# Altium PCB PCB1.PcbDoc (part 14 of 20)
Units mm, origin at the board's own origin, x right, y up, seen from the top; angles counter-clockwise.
Board outline 294.51 x 138.18 mm, 12 copper layers (Top Layer 1 _Signal, L2_GND, L3_Signals, L4_GND, L5_POWER, L6_Signals, L7_GND, L8_Signals, L9_GND, L10_POWER, L11_GND, Bottom Layer_Signals), stack 1.788 mm thick; 1254 components, 836 nets, 5699 pads, 2073 vias.
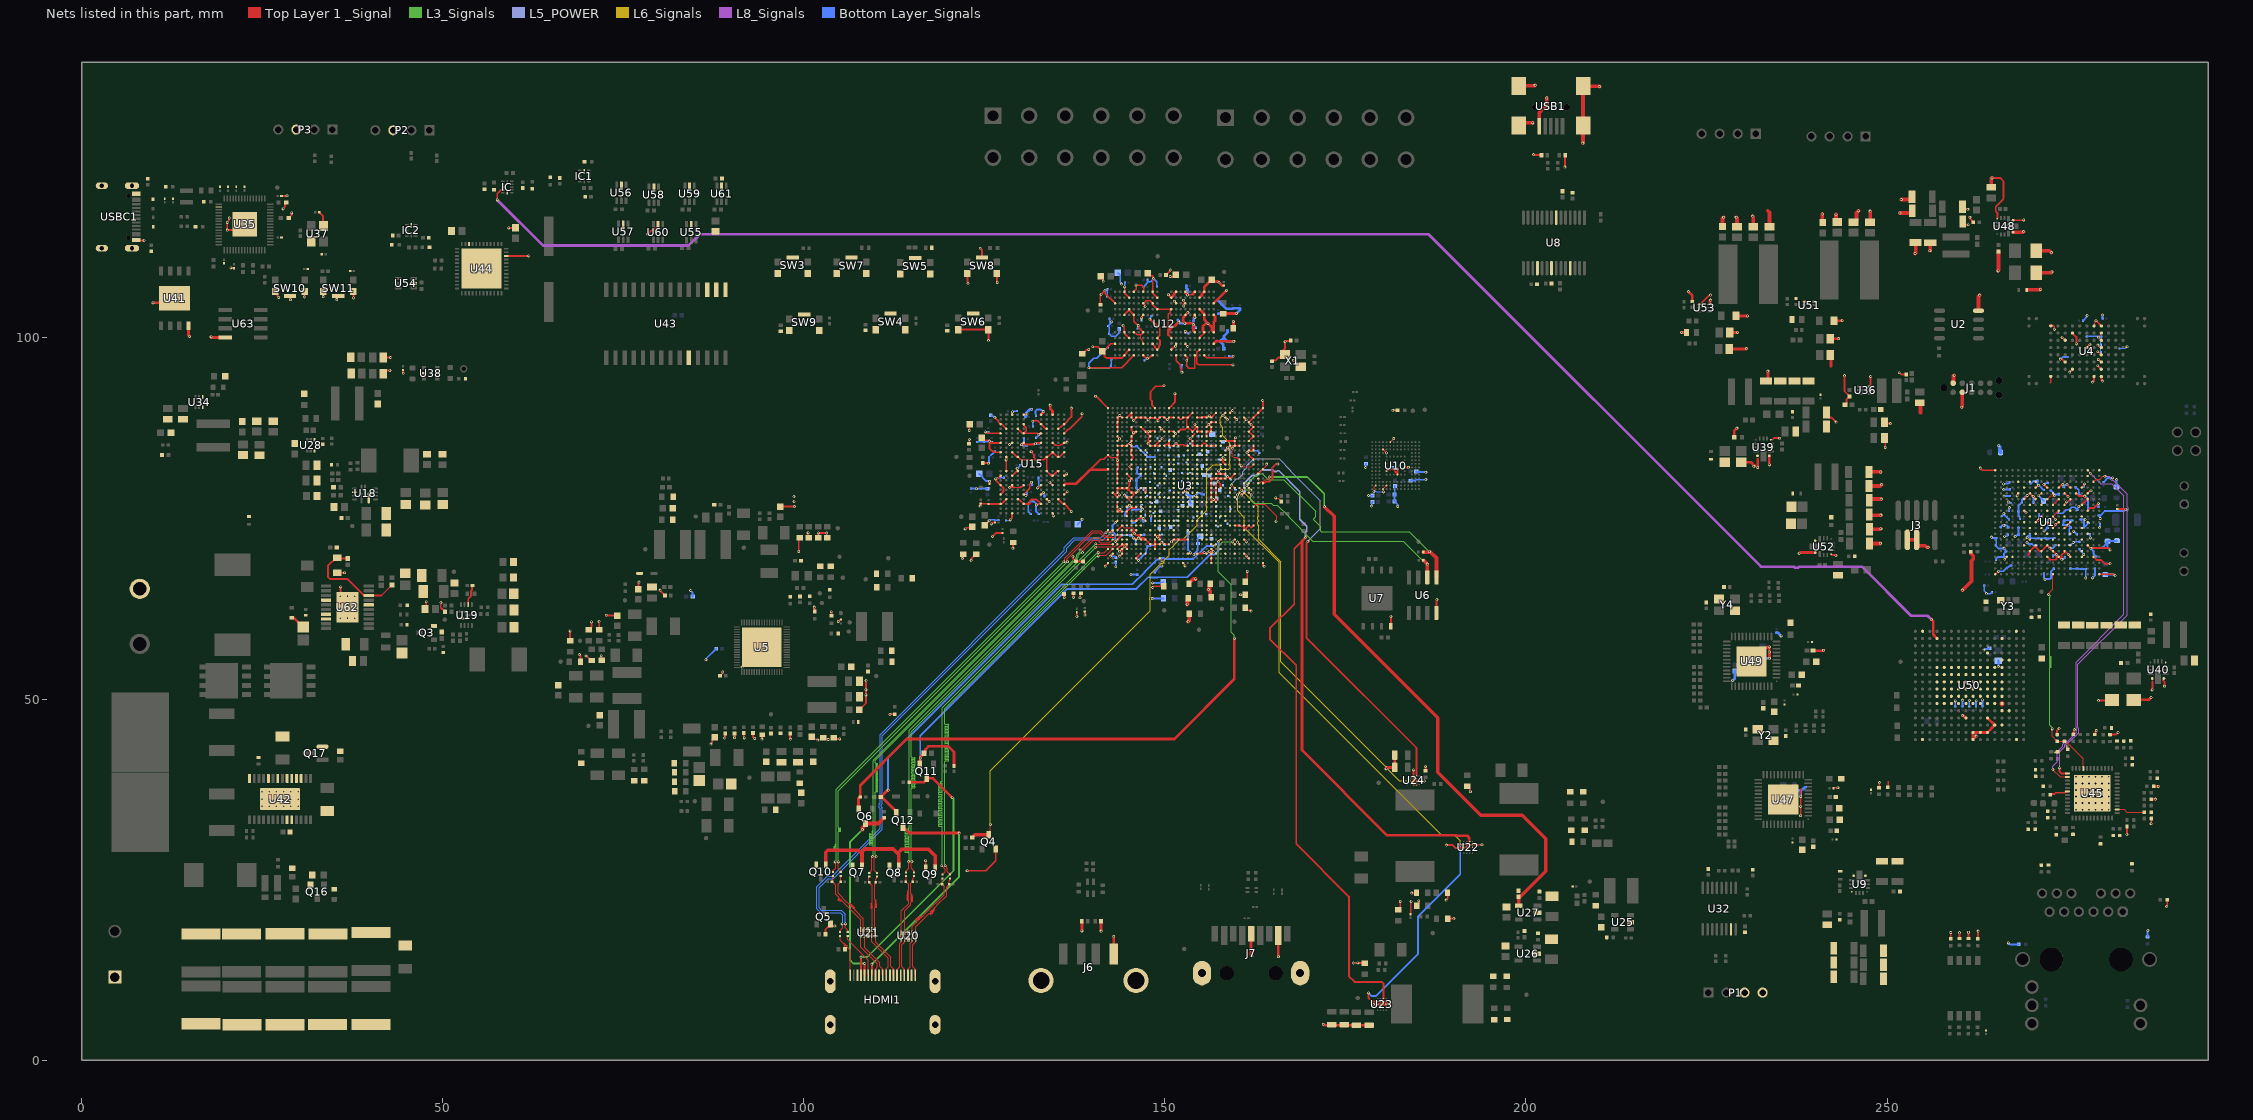
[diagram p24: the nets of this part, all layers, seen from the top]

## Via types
v1: diameter 0.4, hole 0.2, Top Layer 1 _Signal to Bottom Layer_Signals, 2009 vias
v2: diameter 0.508, hole 0.254, Top Layer 1 _Signal to Bottom Layer_Signals, 36 vias
v3: diameter 0.5, hole 0.2, Top Layer 1 _Signal to Bottom Layer_Signals, 12 vias
v4: diameter 1.27, hole 0.711, Top Layer 1 _Signal to Bottom Layer_Signals, 6 vias
v5: diameter 0.3, hole 0.2, Top Layer 1 _Signal to Bottom Layer_Signals, 5 vias
v6: diameter 0.254, hole 0.2, Top Layer 1 _Signal to Bottom Layer_Signals, 3 vias
v7: diameter 0.305, hole 0.2, Top Layer 1 _Signal to Bottom Layer_Signals, 1 vias
v8: diameter 0.254, hole 0.152, Top Layer 1 _Signal to Bottom Layer_Signals, 1 vias

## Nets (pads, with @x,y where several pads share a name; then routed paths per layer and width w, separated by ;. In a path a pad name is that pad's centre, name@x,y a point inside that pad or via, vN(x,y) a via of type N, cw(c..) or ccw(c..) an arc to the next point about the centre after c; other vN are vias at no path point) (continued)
GND: (continued)
  Bottom Layer_Signals w0.254: v1(84.325,65.024) 84.613,64.736 R40.2@84.613,64.197 ; v1(86.437,55.437) 86.465,55.465 86.465,55.562 C175.2@87.879,56.976 ; C424.2@123.168,79.148 123.181,79.135 123.893,79.135 v1(123.913,79.116) ; v1@123.893,79.148 123.929,79.113 124.764,79.113 124.782,79.132 125.41,79.132 C551.2@125.423,79.118 ; C413.2@124.27,81.195 125.286,80.179 125.702,80.179 v1(125.73,80.151) ; v1(125.557,82.641) 125.557,82.648 125.639,82.73 C403.2@125.639,83.442 125.652,83.455 125.652,83.513 126.033,83.895 126.106,83.895 126.479,84.267 C404.2@126.489,84.267 ; v1(125.657,74.692) 125.697,74.692 125.832,74.828 126.45,74.828 126.52,74.757 126.964,74.757 C419.2@126.966,74.76 ; v1(126.574,80.474) 126.613,80.474 126.774,80.634 C408.2@127.736,80.634 ; v1(128.899,89.753) 128.939,89.753 129.022,89.836 129.533,89.836 C427.2@129.546,89.849 ; v1(129.535,81.93) 129.563,81.958 129.606,81.958 129.941,82.293 129.941,82.351 C411.2@129.954,82.364 ; C405.2@130.521,86.05 130.508,86.037 130.508,85.597 130.157,85.246 v1(130.157,85.207) 130.197,85.207 130.282,85.122 C406.2@130.876,85.122 ; v1(130.752,78.181) 130.752,78.22 130.928,78.396 130.928,78.63 C418.2@130.941,78.643 ; C426.2@131.435,75.628 131.425,75.628 131.246,75.808 131.198,75.808 131.074,75.931 131.074,77.125 131.291,77.342 131.918,77.342 132.159,77.101 132.159,77.041 132.2,77 132.2,76.897 v1(132.228,76.869) 132.228,76.829 132.178,76.779 132.178,75.943 132.301,75.82 132.349,75.82 132.529,75.641 C423.2@132.539,75.641 ; v1(131.522,80.023) 131.522,79.984 131.6,79.907 131.6,79.637 C400.2@131.613,79.624 ; C422.2@132.138,89.223 132.128,89.223 132.115,89.236 132.115,89.446 132.11,89.451 132.11,89.926 132.259,90.075 132.788,90.075 132.831,90.031 132.889,90.031 133.116,89.803 v1(133.156,89.803) ; v1(132.381,79.242) 132.381,79.282 132.534,79.435 132.534,80.285 132.492,80.327 132.492,80.672 C396.2@132.479,80.685 ; v1(133.17,78.615) 133.17,78.575 133.298,78.448 133.298,78.087 C416.2@133.311,78.074 ; C394.2@137.945,74.178 138.486,74.72 138.486,74.852 v1(138.532,74.898) ; v1(143.14,71.82) 143.14,72.827 142.728,73.239 142.728,73.982 143.152,74.407 v1(143.152,74.424) ; R104.2@143.951,72.673 145.28,72.673 145.641,72.312 v1(145.681,72.312) 145.681,72.284 145.964,72.001 C17.1@145.964,71.489 ; v1(144.398,78.237) 144.426,78.209 144.654,78.209 144.923,77.94 C284.1@144.933,77.94 ; v1(145.184,85.379) 145.212,85.351 145.212,85.296 145.569,84.939 145.909,84.939 145.985,85.014 146.158,85.014 C298.1@146.171,85.027 ; v1(145.313,67.26) 145.325,67.248 146.165,67.248 R176.2@146.177,67.236 ; C203.2@145.508,74.398 145.508,74.444 145.512,74.448 145.869,74.448 146.401,74.98 v1@146.965,74.98 ; C32.2@145.525,76.232 146.792,76.232 146.853,76.294 v1(146.893,76.294) ; C292.2@146.067,80.265 C292.2@146.076,80.265 ; C298.1@146.171,85.029 C298.1@146.171,85.027 ; C287.2@146.217,82.05 146.171,82.05 146.167,82.046 146.167,81.615 146.124,81.573 146.124,81.362 146.343,81.143 146.502,81.143 146.668,80.978 C291.1@146.668,80.968 146.668,80.958 146.117,80.407 146.117,80.269 146.113,80.265 C292.2@146.076,80.265 ; v1(146.3,78.808) 146.272,78.836 146.272,78.993 146.078,79.186 C290.1@146.078,79.196 146.073,79.202 146.073,80.262 C292.2@146.076,80.265 ; v1(146.339,72.281) 146.367,72.309 146.367,72.399 146.684,72.716 147.09,72.716 147.103,72.729 C471.1@147.103,72.739 ; v1@146.956,74.989 v1@146.965,74.98 ; v1(147.004,74.98) v1@146.965,74.98 ; C310.1@147.065,74.552 147.055,74.552 147.042,74.565 147.042,74.903 v1@146.965,74.98 ; v1(148.072,75.34) 148.08,75.333 148.08,74.675 C462.1@148.087,74.668 ; v1(148.254,63.913) 149.799,63.913 C237.2@149.813,63.926 ; v1(148.297,66.082) 149.655,66.082 C238.2@149.776,66.203 ; C308.1@148.58,83.528 147.614,83.528 146.184,84.958 146.184,85.014 C298.1@146.171,85.027 ; R91.1@148.595,67.58 148.595,67.605 148.643,67.653 148.668,67.653 148.859,67.844 148.859,67.867 149.329,68.336 149.478,68.336 149.558,68.416 v1(149.597,68.416) ; C263.1@153.081,78.376 153.081,78.351 153.204,78.228 153.411,78.228 ; C264.2@153.217,73.008 153.217,70.634 153.57,70.281 v1(153.57,70.242) ; C263.1@153.295,78.344 153.411,78.228 ; C247.2@153.586,77.092 153.494,77.184 153.494,78.145 153.411,78.228 ; C229.2@155.43,78.324 155.417,78.337 155.036,78.337 154.868,78.505 154.658,78.505 154.286,78.134 153.53,78.134 153.436,78.228 153.411,78.228 ; v1(158.698,84.801) 158.726,84.773 158.726,84.563 159.086,84.202 C455.1@159.086,84.157 ; v1(177.795,82.059) 177.815,82.08 177.815,82.567 C216.1@177.836,82.588 ; v1(178.198,78.183) 178.227,78.155 C211.1@178.759,78.155 ; v1(178.622,76.704) 178.65,76.732 178.65,77.189 C214.1@178.745,77.284 ; C207.1@181.506,81.981 181.594,81.893 182.185,81.893 v1(182.213,81.865) ; C217.1@181.87,79.475 181.831,79.435 181.831,78.336 C213.1@181.791,78.296 181.787,78.292 181.787,77.361 C210.1@181.782,77.357 181.802,77.357 182.214,76.945 182.214,76.71 v1(182.242,76.682) ; C209.2@184.019,80.211 184.044,80.236 184.65,80.236 184.777,80.363 186.143,80.363 v1(186.154,80.375) ; C208.1@184.808,81.494 184.876,81.426 186.108,81.426 v1(186.136,81.398) ; C614.1@259.443,48.986 259.443,49.673 259.444,49.674 v1(259.444,49.75) ; C615.2@260.464,48.979 v1(260.464,49.851) v1@260.469,49.856 ; C613.1@261.385,48.99 261.385,49.8 v1(261.399,49.814) ; C617.2@262.336,48.994 262.34,48.998 262.34,49.747 v1(262.355,49.761) ; v1(263.22,49.871) 263.22,49.851 263.232,49.839 C616.2@263.232,49.016 ; v1(263.412,56.779) 263.558,56.925 264.055,56.925 C611.1@264.178,57.048 ; v1(264.457,72.426) 264.463,72.426 264.589,72.299 C119.2@265.132,72.299 265.132,71.314 265.075,71.256 265.088,71.243 265.088,71.223 265.203,71.108 265.203,71.059 265.418,70.845 266.107,70.845 266.164,70.902 v1(266.204,70.902) 266.204,70.863 266.388,70.679 266.388,70.356 C81.2@266.401,70.343 266.401,70.333 266.196,70.128 266.196,69.676 ; C113.2@265.073,69.275 265.086,69.288 265.086,69.298 265.202,69.413 265.202,69.462 265.416,69.676 266.196,69.676 ; C619.1@265.403,55.319 265.416,55.306 v1(265.416,54.488) ; v1(265.452,67.682) 266.075,67.682 266.635,68.242 266.763,68.242 266.991,68.47 267.189,68.47 267.202,68.483 C114.2@267.202,68.493 ; C78.2@265.752,73.827 265.762,73.827 265.971,74.036 266.152,74.036 v1(266.18,74.064) 266.207,74.036 266.588,74.036 266.844,73.78 C83.2@266.844,73.77 C83.2@266.857,73.757 ; C85.2@265.897,75.316 265.907,75.316 266.156,75.565 266.156,75.656 v1(266.184,75.684) 266.184,75.585 266.916,74.853 C79.2@266.916,74.843 ; v1(266.13,79.798) 266.751,79.798 266.956,80.004 266.966,80.004 266.979,80.017 C108.2@266.979,80.027 ; v1(266.15,79.006) 266.156,79.013 266.987,79.013 267.001,79.027 267.011,79.027 267.024,79.04 C82.2@267.024,79.05 ; v1(266.2,78.098) 267.034,78.098 267.047,78.111 C80.2@267.047,78.114 ; v1(266.265,72.517) 266.293,72.545 266.573,72.545 266.764,72.736 C84.2@266.764,72.746 ; v1(266.308,69.361) 266.304,69.365 266.304,69.676 266.196,69.676 ; v1(266.783,16.228) 266.823,16.228 267.023,16.028 R399.2@268.241,16.028 ; v1(266.785,77.28) 266.813,77.252 267.004,77.252 267.085,77.171 267.095,77.171 267.108,77.158 C86.2@267.108,77.148 ; C87.2@266.868,76.02 266.881,76.033 266.881,76.402 266.948,76.469 v1(266.948,76.509) ; v1(267.724,72.491) 267.727,72.491 267.903,72.667 268.194,72.667 268.207,72.68 C145.2@268.207,72.69 268.212,72.695 268.212,73.743 268.218,73.748 C148.2@268.218,73.766 ; C144.2@268.39,74.922 268.377,74.935 268.377,75.246 268.209,75.413 C150.2@268.209,75.944 268.209,76.769 268.663,77.223 C142.2@268.663,77.233 268.676,77.246 268.676,77.573 269.283,78.18 v1(269.414,78.18) ; v1(269.379,71.652) 269.419,71.652 269.591,71.48 269.981,71.48 270.006,71.454 270.055,71.454 270.222,71.287 270.69,71.287 270.703,71.274 C191.2@270.703,71.264 ; v1(269.406,72.325) 269.434,72.353 269.434,72.454 269.803,72.823 C143.2@269.813,72.823 269.813,72.409 269.962,72.26 270.956,72.26 270.958,72.258 C152.2@270.979,72.258 271.893,72.258 271.957,72.195 C151.2@271.967,72.195 271.98,72.208 272.491,72.208 272.547,72.263 C138.2@273.186,72.263 ; C107.2@269.896,79.82 269.896,79.83 270.298,80.232 C95.2@270.848,80.232 270.848,79.772 270.987,79.634 v1(270.987,79.594) 271.015,79.566 271.061,79.566 271.713,78.914 C134.2@271.723,78.914 ; v1(270.227,78.083) 270.293,78.017 C147.2@270.293,77.167 ; v1(271.015,78.148) 271.015,78.145 271.683,77.477 C121.1@271.683,77.423 ; v1(271.71,79.696) 271.75,79.696 271.931,79.878 272.265,79.878 272.278,79.891 C93.2@272.278,79.901 ; C102.2@271.74,67.378 271.74,66.747 271.874,66.612 v1(271.874,66.573) 271.902,66.601 272.568,66.601 272.717,66.749 272.717,67.667 273.076,68.026 273.086,68.026 C96.2@273.099,68.039 ; v1(272.554,70.902) 272.947,70.902 273.343,71.299 C123.2@273.343,71.309 ; C135.2@272.664,78.863 272.674,78.863 272.752,78.785 272.8,78.785 273.201,78.384 v1(273.201,78.177) 273.241,78.177 273.391,78.327 273.805,78.327 273.818,78.34 C116.2@273.818,78.35 ; C129.2@272.988,69.885 273.001,69.898 273.346,69.898 273.449,70.002 v1(273.488,70.002) ; v1(273.993,97.069) 274.032,97.069 274.322,97.358 C11.1@274.987,97.358 ; v1(274.201,69.351) 274.229,69.379 274.41,69.379 274.64,69.61 C154.2@274.65,69.61 ; C130.2@274.411,74.089 v1@275.063,74.088 ; C104.2@274.432,79.369 274.432,79.379 274.663,79.61 274.663,79.66 274.894,79.66 v1(274.922,79.688) ; v1@275.102,73.996 275.229,73.996 275.449,73.777 C140.2@275.449,73.767 275.449,73.757 275.239,73.547 275.239,72.791 C127.2@275.243,72.787 ; C122.2@275.211,71.344 275.211,71.354 275.224,71.367 275.467,71.367 275.772,71.672 v1(275.812,71.672) 275.851,71.672 275.951,71.772 C139.2@276.665,71.772 ; C100.2@275.379,68.045 275.382,68.048 276.374,68.048 C131.2@276.377,68.05 276.39,68.037 276.694,68.037 276.724,68.007 277.052,68.007 ; v1(275.808,73.215) 275.836,73.188 275.914,73.188 276.273,72.828 C153.2@276.273,72.818 ; C99.2@276.107,79.335 276.107,79.325 276.38,79.051 276.478,79.051 276.557,78.972 276.557,78.484 276.583,78.458 276.583,78.448 276.788,78.243 276.788,78.103 277.374,78.103 v1(277.377,78.1) 277.405,78.072 277.535,78.072 277.825,77.783 277.825,76.942 277.808,76.926 C155.2@277.808,76.158 ; C190.2@276.635,70.759 276.635,70.749 276.763,70.62 276.763,70.541 277.209,70.096 277.209,70.073 277.238,70.043 v1(277.238,70.023) ; C156.2@276.773,74.876 277.352,74.876 277.395,74.832 v1(277.435,74.832) 277.435,74.793 277.274,74.632 C136.2@277.274,73.784 ; 277.056,68.007 277.192,68.007 277.195,68.004 277.511,68.004 v1(277.511,66.757) ; C14.1@277.143,102.382 277.143,102.392 277.677,102.926 277.677,103.07 v1(277.705,103.098) ; C136.2@277.274,73.774 C136.2@277.274,73.784 ; C105.2@277.282,79.4 277.289,79.4 277.302,79.413 277.302,79.763 v1(277.323,79.784) ; C103.2@277.512,68.004 C103.2@277.525,67.991 ; C13.1@277.66,100.226 v1@279.32,100.226 ; C98.2@277.935,74.393 277.925,74.393 277.329,73.797 277.287,73.797 C136.2@277.274,73.784 ; C149.2@278.123,72.818 278.136,72.805 278.136,72.368 278.152,72.351 278.152,72.328 v1(278.16,72.321) ; v1(278.225,70.875) 278.225,70.835 278.594,70.467 278.594,70.085 278.843,69.836 278.879,69.836 278.958,69.757 C92.2@278.968,69.757 ; v1(278.461,66.773) 278.813,67.125 278.813,67.902 278.809,67.906 278.809,68.027 278.796,68.04 C101.2@278.786,68.04 ; v1(279.269,77.098) 279.284,77.082 279.284,76.61 C94.2@279.297,76.597 ; v1@279.359,100.13 279.375,100.13 279.442,100.196 279.693,100.196 C9.1@279.706,100.209 ; v1(279.438,73.74) 279.438,73.779 279.482,73.823 279.482,74.194 C89.2@279.495,74.207 ; v1(279.527,74.996) 279.499,75.024 279.499,75.224 279.299,75.425 C90.2@279.299,75.435 279.299,75.445 279.312,75.458 279.588,75.458 280.179,76.048 C111.2@280.189,76.048 282.852,76.048 v1(283.07,76.266) ; v1(279.829,103.179) 279.829,103.139 279.859,103.11 279.859,102.706 C6.1@279.872,102.693 ; C91.2@279.843,70.956 279.853,70.956 280.299,71.402 C133.1@280.299,71.627 ; C112.2@279.972,80.024 279.982,80.024 280.569,80.611 v1(281.229,80.611) ; C106.1@280.212,67.222 281.406,67.222 281.547,67.081 v1(281.586,67.081) ; v1(280.881,70.656) 280.881,70.696 280.542,71.035 280.542,71.627 C133.1@280.299,71.627 ; C97.1@281.773,79.356 281.773,80.371 v1(281.787,80.385) 281.796,80.385 v1@281.801,80.38 ; C132.1@281.836,71.921 281.799,71.884 280.579,71.884 C133.1@280.542,71.846 280.518,71.846 C133.1@280.299,71.627 ; C380.2@286.073,17.075 286.073,17.876 286.124,17.928 v1(286.124,17.967)
  Bottom Layer_Signals w0.381: C428.2@130.683,89.055 130.799,89.171 130.799,89.578 131.351,90.13 v1(131.566,90.13) ; C319.2@151.792,102.479 151.896,102.376 151.896,102.228 152.096,102.028 152.776,102.028 v1(152.78,102.024) ; C320.2@152.963,107.235 152.963,106.903 153.128,106.738 153.128,105.971 v1(153.132,105.967) ; C332.2@153.997,102.35 153.997,102.677 154.15,102.83 v1(154.15,102.835) ; C333.2@157.407,103.355 158.635,103.355 158.679,103.398 v1(159.912,103.398) 160.389,103.875 C358.2@160.389,104.054 160.321,104.122 159.431,104.122 C345.2@159.341,104.032 158.515,104.032 C357.2@157.445,105.102 ; C388.2@158.141,98.504 158.072,98.573 158.072,99.084 157.771,99.385 C342.2@157.771,99.7 157.846,99.625 158.18,99.959 ; C331.2@158.667,101.052 158.667,100.762 158.18,100.275 158.18,99.959 ; v1(159.549,99.54) 158.599,99.54 158.18,99.959 ; v1(228.628,52.58) 228.679,52.58 228.9,52.801 C661.1@228.9,53.887 ; C658.2@232.81,55.863 233.03,55.643 233.715,55.643 v1(233.718,55.64) ; C662.2@234.675,59.176 234.888,59.176 235.334,58.73 v1(235.339,58.73) ; C24.2@235.619,36.638 235.879,36.897 236.011,36.897 236.015,36.901 236.772,36.901 237.192,37.322 C27.1@237.192,37.366 238.04,37.366 238.049,37.357 v1(238.049,36.515) ; 238.089,37.321 238.305,37.537 238.402,37.537 238.614,37.749 238.654,37.749 C28.2@238.697,37.792
  Bottom Layer_Signals w0.508: v1(265.47,85.063) 265.621,84.912 265.621,84.25 C88.1@265.717,84.154
  other v1: 238.036,35.125 24.979,35.146 25.979,35.146 26.979,35.146 27.98,35.146 28.98,35.146 29.98,35.146 24.979,36.146 25.979,36.146 26.979,36.146 27.98,36.146 28.98,36.146 29.98,36.146 24.979,37.146 25.979,37.146 26.979,37.146 27.98,37.146 28.98,37.146 29.98,37.146 263.775,64.584 98.652,77.366 98.622,78.026
  other v2: 276.149,34.678 277.059,34.678 277.969,34.678 278.879,34.678 279.789,34.678 280.699,34.678 276.149,35.588 277.059,35.588 277.969,35.588 278.879,35.588 279.789,35.588 280.699,35.588 276.149,36.498 277.059,36.498 277.969,36.498 278.879,36.498 279.789,36.498 280.699,36.498 276.149,37.408 277.059,37.408 277.969,37.408 278.879,37.408 279.789,37.408 280.699,37.408 276.149,38.318 277.059,38.318 277.969,38.318 278.879,38.318 279.789,38.318 280.699,38.318 276.149,39.228 277.059,39.228 277.969,39.228 278.879,39.228 279.789,39.228 280.699,39.228
  other v3: 35.818,61.211 36.818,61.211 37.818,61.211 35.818,62.211 36.818,62.211 37.818,62.211 35.818,63.211 36.818,63.211 37.818,63.211 36.818,64.211 37.818,64.211
HB_LM: C219.2 D9.1 U62.18 | length 2.1
  Top Layer 1 _Signal w0.381: D9.1@29.084,61.237 29.103,61.217 29.415,61.217 30.672,59.961 C219.2@30.697,59.961
HDMI0_eARC+: C465.1 HDMI1.14 | length 6.6
  Top Layer 1 _Signal w0.161: C465.1@106.082,17.213 106.082,16.659 108.925,13.816 HDMI1.14@108.925,11.745
HDMI0_eARC-: C469.1 HDMI1.19 R103.2 | length 6.7
  Top Layer 1 _Signal w0.161: C469.1@105.035,17.218 105.035,16.62 105.208,16.447 105.265,16.39 105.52,16.134 105.577,16.191 105.709,16.059 105.576,15.925 105.708,15.793 105.866,15.951 105.998,15.819 105.916,15.738 106.049,15.606 106.106,15.549 106.425,15.23 HDMI1.19@106.425,11.745
HDMI0_TX0_PORT/eDP0_TX_D0_N: C479.1 U3.AJ1 | length 66.8
  Top Layer 1 _Signal w0.111: C479.1@109.074,25.932 109.43,26.288 109.43,28.066 109.541,28.176 v1(109.541,28.179) ; v1(138.251,70.622) 138.33,70.622 138.436,70.728 138.442,70.728 139.945,72.232 140.052,72.339 140.844,72.339 141.105,72.078 U3.AJ1@142.129,72.078
  L3_Signals w0.092: v1(109.541,28.179) 109.541,28.263 109.635,28.357 109.635,29.258 109.636,29.259 109.636,29.704 109.636,29.75 ccw(c109.544,29.75) 109.544,29.842 109.134,29.842 cw(c109.134,29.927) 109.134,30.011 109.552,30.011 ccw(c109.552,30.095) 109.552,30.18 109.134,30.18 cw(c109.134,30.264) 109.134,30.348 109.552,30.348 ccw(c109.552,30.433) 109.552,30.517 109.134,30.517 cw(c109.134,30.601) 109.134,30.686 109.552,30.686 ccw(c109.552,30.77) 109.552,30.854 109.134,30.854 cw(c109.134,30.939) 109.134,31.023 109.552,31.023 ccw(c109.552,31.107) 109.552,31.192 109.134,31.192 cw(c109.134,31.276) 109.134,31.36 109.552,31.36 ccw(c109.552,31.445) 109.552,31.529 109.529,31.529 cw(c109.529,31.613) 109.529,31.698 109.544,31.698 ccw(c109.544,31.79) 109.636,31.79 109.636,32.143 109.636,38.059 109.636,39.383 109.636,41.472 109.641,41.472 109.696,41.526 109.696,41.57 137.816,69.69 137.816,69.982 138.207,70.373 138.207,70.578 v1(138.251,70.622)
HDMI0_TX0_PORT/eDP0_TX_D0_P: C478.1 U3.AJ2 | length 67.2
  Top Layer 1 _Signal w0.111: v1(110.024,28.179) 109.77,27.925 109.77,26.29 C478.1@110.126,25.934 ; v1(138.593,70.28) 138.649,70.335 138.649,70.563 140.085,71.999 140.703,71.999 141.085,71.618 142.319,71.618 U3.AJ2@142.779,72.078
  L3_Signals w0.092: v1(110.024,28.179) 110.024,28.263 109.93,28.357 109.93,29.135 109.932,29.137 109.932,36.875 109.932,37.09 cw(c110.024,37.09) 110.024,37.182 110.133,37.182 ccw(c110.133,37.267) 110.133,37.351 110.016,37.351 cw(c110.016,37.435) 110.016,37.52 110.133,37.52 ccw(c110.133,37.604) 110.133,37.688 110.016,37.688 cw(c110.016,37.773) 110.016,37.857 110.133,37.857 ccw(c110.133,37.941) 110.133,38.026 110.016,38.026 cw(c110.016,38.11) 110.016,38.194 110.133,38.194 ccw(c110.133,38.279) 110.133,38.363 110.016,38.363 cw(c110.016,38.447) 110.016,38.532 110.133,38.532 ccw(c110.133,38.616) 110.133,38.7 110.016,38.7 cw(c110.016,38.785) 110.016,38.869 110.133,38.869 ccw(c110.133,38.953) 110.133,39.038 110.016,39.038 cw(c110.016,39.122) 110.016,39.206 110.133,39.206 ccw(c110.133,39.291) 110.133,39.375 110.016,39.375 cw(c110.016,39.459) 110.016,39.544 110.133,39.544 ccw(c110.133,39.628) 110.133,39.712 110.016,39.712 cw(c110.016,39.797) 110.016,39.881 110.133,39.881 ccw(c110.133,39.965) 110.133,40.05 110.016,40.05 cw(c110.016,40.134) 110.016,40.218 110.133,40.218 ccw(c110.133,40.303) 110.133,40.387 110.016,40.387 cw(c110.016,40.471) 110.016,40.556 110.133,40.556 ccw(c110.133,40.64) 110.133,40.724 110.016,40.724 cw(c110.016,40.809) 110.016,40.893 110.133,40.893 ccw(c110.133,40.977) 110.133,41.062 110.024,41.062 cw(c110.024,41.154) 109.932,41.154 109.932,41.35 109.89,41.392 109.89,41.489 138.01,69.61 138.01,69.901 138.344,70.235 138.549,70.235 v1(138.593,70.28)
HDMI0_TX0_PORT_N: C479.2 HDMI1.9 R109.2 U21.2 U21.9 | length 16
  Top Layer 1 _Signal w0.111: C479.2@109.074,25.402 109.024,25.351 109.024,24.709 109.212,24.521 109.212,24.453 109.515,24.15 109.515,21.993 109.515,21.801 cw(c109.404,21.801) 109.404,21.69 109.346,21.69 ccw(c109.346,21.622) 109.346,21.554 109.447,21.554 cw(c109.447,21.485) 109.447,21.417 109.346,21.417 ccw(c109.346,21.349) 109.346,21.281 109.449,21.281 cw(c109.449,21.213) 109.449,21.144 109.365,21.144 ccw(c109.365,21.076) 109.365,21.008 109.404,21.008 cw(c109.404,20.897) 109.515,20.897 109.515,20.19 109.515,18.426 109.45,18.361 109.444,18.361 109.399,18.317 U21.9@109.399,17.218 109.399,16.418 111.7,14.117 111.7,12.898 111.449,12.647 111.449,11.769 HDMI1.9@111.426,11.745
HDMI0_TX0_PORT_P: C478.2 HDMI1.7 R110.2 U21.1 U21.10 | length 16
  Top Layer 1 _Signal w0.111: C478.2@110.126,25.404 110.123,25.4 110.123,25.189 109.954,25.02 R110.2@109.954,24.655 109.916,24.617 109.916,24.378 109.855,24.317 109.855,22.791 109.855,22.243 ccw(c109.966,22.243) 109.966,22.132 cw(c109.966,22.064) 109.966,21.995 109.923,21.995 ccw(c109.923,21.927) 109.923,21.859 109.967,21.859 cw(c109.967,21.791) 109.967,21.723 109.923,21.723 ccw(c109.923,21.654) 109.923,21.586 110.029,21.586 cw(c110.029,21.518) 110.029,21.45 109.923,21.45 ccw(c109.923,21.382) 109.923,21.313 110.029,21.313 cw(c110.029,21.245) 110.029,21.177 109.966,21.177 ccw(c109.966,21.066) 109.855,21.066 109.855,20.874 109.855,18.129 U21.1@109.899,18.084 U21.10@109.899,17.218 109.944,17.174 109.944,16.887 109.955,16.876 109.955,16.343 112.04,14.257 112.04,12.987 112.384,12.642 112.384,11.787 HDMI1.7@112.426,11.745
HDMI0_TX1_PORT/eDP0_TX_D1_N: C477.1 U3.AK2 | length 67.5
  Top Layer 1 _Signal w0.111: C477.1@114.173,25.994 114.173,26.189 114.547,26.563 114.547,27 114.553,27.006 114.553,27.286 114.536,27.303 114.536,27.44 v1(114.481,27.496) ; v1(140.423,71.495) 140.495,71.423 142.559,71.423 142.564,71.428 U3.AK2@142.779,71.428
  L3_Signals w0.092: v1(114.481,27.496) 114.607,27.622 114.607,28.603 114.607,28.649 ccw(c114.497,28.649) 114.497,28.759 114.07,28.759 cw(c114.07,28.868) 114.07,28.978 114.497,28.978 ccw(c114.497,29.088) 114.497,29.197 114.07,29.197 cw(c114.07,29.307) 114.07,29.417 114.497,29.417 ccw(c114.497,29.527) 114.497,29.636 114.07,29.636 cw(c114.07,29.746) 114.07,29.856 114.497,29.856 ccw(c114.497,29.966) 114.497,30.075 114.07,30.075 cw(c114.07,30.185) 114.07,30.295 114.497,30.295 ccw(c114.497,30.405) 114.497,30.514 114.07,30.514 cw(c114.07,30.624) 114.07,30.734 114.497,30.734 ccw(c114.497,30.843) 114.497,30.953 114.07,30.953 cw(c114.07,31.063) 114.07,31.173 114.497,31.173 ccw(c114.497,31.282) 114.497,31.392 114.07,31.392 cw(c114.07,31.502) 114.07,31.612 114.497,31.612 ccw(c114.497,31.721) 114.497,31.831 114.176,31.831 cw(c114.176,31.941) 114.176,32.05 114.497,32.05 ccw(c114.497,32.16) 114.607,32.16 114.607,32.506 114.607,45.662 140.423,71.478 v1(140.423,71.495)
HDMI0_TX1_PORT/eDP0_TX_D1_P: C476.1 U3.AK3 | length 67.5
  Top Layer 1 _Signal w0.111: v1(114.965,27.496) 114.91,27.44 114.91,27.303 114.893,27.286 114.893,26.865 114.886,26.859 114.886,26.568 115.26,26.194 C476.1@115.26,25.999 ; v1(140.423,71.011) 140.495,71.083 143.085,71.083 U3.AK3@143.429,71.428
  L3_Signals w0.092: v1(114.965,27.496) 114.903,27.558 114.903,37.332 114.903,37.598 cw(c115.013,37.598) 115.013,37.707 115.313,37.707 ccw(c115.313,37.817) 115.313,37.927 115.013,37.927 cw(c115.013,38.037) 115.013,38.146 115.313,38.146 ccw(c115.313,38.256) 115.313,38.366 115.013,38.366 cw(c115.013,38.475) 115.013,38.585 115.313,38.585 ccw(c115.313,38.695) 115.313,38.805 115.013,38.805 cw(c115.013,38.914) 115.013,39.024 115.313,39.024 ccw(c115.313,39.134) 115.313,39.244 115.013,39.244 cw(c115.013,39.353) 115.013,39.463 115.313,39.463 ccw(c115.313,39.573) 115.313,39.682 115.013,39.682 cw(c115.013,39.792) 115.013,39.902 115.313,39.902 ccw(c115.313,40.012) 115.313,40.121 115.013,40.121 cw(c115.013,40.231) 115.013,40.341 115.313,40.341 ccw(c115.313,40.451) 115.313,40.56 115.013,40.56 cw(c115.013,40.67) 115.013,40.78 115.313,40.78 ccw(c115.313,40.889) 115.313,40.999 115.013,40.999 cw(c115.013,41.109) 115.013,41.219 115.313,41.219 ccw(c115.313,41.328) 115.313,41.438 115.013,41.438 cw(c115.013,41.548) 115.013,41.658 115.297,41.658 ccw(c115.297,41.767) 115.297,41.877 115.013,41.877 cw(c115.013,41.987) 114.903,41.987 114.903,44.182 114.903,45.491 v1(140.423,71.011)
HDMI0_TX1_PORT_N: C477.2 HDMI1.6 R111.2 U20.5 U20.6 | length 16
  Top Layer 1 _Signal w0.111: HDMI1.6@112.926,11.745 112.926,12.601 113.256,12.931 113.256,16.16 113.488,16.392 U20.6@113.488,16.78 U20.5@113.488,17.645 113.488,20.654 114.504,21.67 114.504,21.982 114.504,22.038 ccw(c114.393,22.038) 114.393,22.149 114.34,22.149 cw(c114.34,22.217) 114.34,22.285 114.435,22.285 ccw(c114.435,22.353) 114.435,22.421 114.34,22.421 cw(c114.34,22.49) 114.34,22.558 114.435,22.558 ccw(c114.435,22.626) 114.435,22.694 114.34,22.694 cw(c114.34,22.762) 114.34,22.831 114.441,22.831 ccw(c114.441,22.899) 114.441,22.967 114.412,22.967 cw(c114.412,23.035) 114.412,23.103 114.435,23.103 ccw(c114.435,23.172) 114.435,23.24 114.393,23.24 cw(c114.393,23.308) 114.393,23.376 ccw(c114.393,23.487) 114.504,23.487 114.504,23.699 114.504,24.348 R111.2@114.132,24.72 114.132,24.951 114.173,24.992 C477.2@114.173,25.464
HDMI0_TX1_PORT_P: C476.2 HDMI1.4 R112.2 U20.4 U20.7 | length 16
  Top Layer 1 _Signal w0.111: HDMI1.4@113.926,11.745 113.926,12.601 113.596,12.931 113.596,15.999 113.988,16.392 U20.7@113.988,16.78 U20.4@113.988,17.645 113.988,20.674 114.843,21.53 114.843,21.667 114.843,21.859 cw(c114.954,21.859) 114.954,21.97 115.034,21.97 ccw(c115.034,22.038) 115.034,22.106 114.911,22.106 cw(c114.911,22.175) 114.911,22.243 115.034,22.243 ccw(c115.034,22.311) 115.034,22.379 114.911,22.379 cw(c114.911,22.447) 114.911,22.516 115.034,22.516 ccw(c115.034,22.584) 115.034,22.652 114.911,22.652 cw(c114.911,22.72) 114.911,22.788 114.976,22.788 ccw(c114.976,22.857) 114.976,22.925 114.954,22.925 cw(c114.954,23.036) 114.843,23.036 114.843,23.226 114.843,24.469 R112.2@115.063,24.689 115.063,25.076 115.26,25.273 C476.2@115.26,25.469
HDMI0_TX2_PORT/eDP0_TX_D2_N: C475.1 U3.AL1 | length 67.5
  Top Layer 1 _Signal w0.111: v1(119.106,26.909) 119.56,26.455 119.56,26.067 C475.1@119.2,25.706 ; v1@140.772,70.298 140.844,70.227 141.578,70.227 U3.AL1@142.129,70.778
  L3_Signals w0.092: v1(119.106,26.909) 119.106,26.993 119.2,27.087 119.2,32.237 119.2,32.284 ccw(c119.078,32.284) 119.078,32.406 118.736,32.406 cw(c118.736,32.528) 118.736,32.651 119.078,32.651 ccw(c119.078,32.773) 119.078,32.896 118.736,32.896 cw(c118.736,33.018) 118.736,33.141 119.078,33.141 ccw(c119.078,33.263) 119.078,33.385 118.736,33.385 cw(c118.736,33.508) 118.736,33.63 119.078,33.63 ccw(c119.078,33.753) 119.078,33.875 118.736,33.875 cw(c118.736,33.998) 118.736,34.12 119.078,34.12 ccw(c119.078,34.242) 119.078,34.365 118.736,34.365 cw(c118.736,34.487) 118.736,34.61 119.078,34.61 ccw(c119.078,34.732) 119.078,34.855 118.736,34.855 cw(c118.736,34.977) 118.736,35.099 119.078,35.099 ccw(c119.078,35.222) 119.078,35.344 118.736,35.344 cw(c118.736,35.467) 118.736,35.589 119.078,35.589 ccw(c119.078,35.712) 119.078,35.834 118.736,35.834 cw(c118.736,35.956) 118.736,36.079 119.078,36.079 ccw(c119.078,36.201) 119.078,36.324 118.736,36.324 cw(c118.736,36.446) 118.736,36.569 119.078,36.569 ccw(c119.078,36.691) 119.078,36.813 118.736,36.813 cw(c118.736,36.936) 118.736,37.058 119.078,37.058 ccw(c119.078,37.181) 119.078,37.303 118.736,37.303 cw(c118.736,37.426) 118.736,37.548 119.078,37.548 ccw(c119.078,37.67) 119.078,37.793 118.736,37.793 cw(c118.736,37.915) 118.736,38.038 119.078,38.038 ccw(c119.078,38.16) 119.078,38.283 119.041,38.283 cw(c119.041,38.405) 119.041,38.527 119.078,38.527 ccw(c119.078,38.65) 119.2,38.65 119.2,39.048 119.2,48.783 140.716,70.299 v1(140.772,70.299)
HDMI0_TX2_PORT/eDP0_TX_D2_P: C474.1 U3.AL2 | length 67.4
  Top Layer 1 _Signal w0.111: v1(119.59,26.909) 119.9,26.6 119.9,26.05 C474.1@120.261,25.689 ; v1(140.772,69.815) 140.844,69.887 141.888,69.887 U3.AL2@142.779,70.778
  L3_Signals w0.092: v1(119.59,26.909) 119.59,26.993 119.496,27.087 119.496,41.057 119.496,41.323 cw(c119.606,41.323) 119.606,41.433 119.968,41.433 ccw(c119.968,41.543) 119.968,41.652 119.606,41.652 cw(c119.606,41.762) 119.606,41.872 119.968,41.872 ccw(c119.968,41.982) 119.968,42.091 119.606,42.091 cw(c119.606,42.201) 119.606,42.311 119.968,42.311 ccw(c119.968,42.42) 119.968,42.53 119.606,42.53 cw(c119.606,42.64) 119.606,42.75 119.968,42.75 ccw(c119.968,42.859) 119.968,42.969 119.606,42.969 cw(c119.606,43.079) 119.606,43.189 119.968,43.189 ccw(c119.968,43.298) 119.968,43.408 119.606,43.408 cw(c119.606,43.518) 119.606,43.627 119.968,43.627 ccw(c119.968,43.737) 119.968,43.847 119.606,43.847 cw(c119.606,43.957) 119.606,44.066 119.968,44.066 ccw(c119.968,44.176) 119.968,44.286 119.606,44.286 cw(c119.606,44.396) 119.606,44.505 119.968,44.505 ccw(c119.968,44.615) 119.968,44.725 119.606,44.725 cw(c119.606,44.834) 119.606,44.944 119.968,44.944 ccw(c119.968,45.054) 119.968,45.164 119.606,45.164 cw(c119.606,45.273) 119.606,45.383 119.968,45.383 ccw(c119.968,45.493) 119.968,45.603 119.606,45.603 cw(c119.606,45.712) 119.606,45.822 119.968,45.822 ccw(c119.968,45.932) 119.968,46.041 119.606,46.041 cw(c119.606,46.151) 119.606,46.261 119.968,46.261 ccw(c119.968,46.371) 119.968,46.48 119.606,46.48 cw(c119.606,46.59) 119.496,46.59 119.496,47.452 119.496,48.66 140.591,69.756 140.713,69.756 v1(140.772,69.815)
HDMI0_TX2_PORT_N: C475.2 HDMI1.3 R115.2 U20.2 U20.9 | length 17.5
  Top Layer 1 _Signal w0.111: HDMI1.3@114.426,11.745 114.426,12.601 114.756,12.931 114.756,16.16 114.988,16.392 U20.9@114.988,16.78 115.043,16.835 115.043,18.512 115.598,19.066 115.637,19.105 ccw(c115.558,19.184) 115.637,19.262 115.517,19.382 cw(c115.566,19.43) 115.517,19.478 cw(c115.566,19.43) 115.614,19.478 115.764,19.328 ccw(c115.812,19.377) 115.86,19.328 ccw(c115.812,19.377) 115.86,19.425 115.71,19.575 cw(c115.759,19.623) 115.71,19.671 cw(c115.759,19.623) 115.807,19.671 115.957,19.521 ccw(c116.005,19.569) 116.053,19.521 ccw(c116.005,19.569) 116.053,19.618 115.936,19.735 cw(c115.984,19.783) 115.936,19.831 cw(c115.984,19.783) 116.032,19.831 116.149,19.714 ccw(c116.198,19.762) 116.246,19.714 ccw(c116.198,19.762) 116.246,19.811 116.216,19.841 cw(c116.264,19.889) 116.216,19.937 cw(c116.264,19.889) 116.312,19.937 ccw(c116.391,20.016) 116.469,19.937 116.972,20.44 119.456,22.924 119.456,24.086 R115.2@119.163,24.38 119.163,24.61 119.2,24.647 C475.2@119.2,25.176
HDMI0_TX2_PORT_P: C474.2 HDMI1.1 R116.2 U20.1 U20.10 | length 17.5
  Top Layer 1 _Signal w0.111: HDMI1.1@115.426,11.745 115.426,12.601 115.096,12.931 115.096,16 115.488,16.391 U20.10@115.488,16.779 U20.1@115.488,17.645 115.488,18.476 117.145,20.133 117.28,20.268 cw(c117.359,20.19) 117.437,20.268 117.552,20.154 ccw(c117.6,20.202) 117.648,20.154 ccw(c117.6,20.202) 117.648,20.251 117.504,20.395 cw(c117.552,20.443) 117.504,20.492 cw(c117.552,20.443) 117.6,20.492 117.745,20.347 ccw(c117.793,20.395) 117.841,20.347 ccw(c117.793,20.395) 117.841,20.444 117.696,20.588 cw(c117.745,20.636) 117.696,20.684 cw(c117.745,20.636) 117.793,20.684 117.906,20.571 ccw(c117.955,20.619) 118.003,20.571 ccw(c117.955,20.619) 118.003,20.667 117.889,20.781 cw(c117.938,20.829) 117.889,20.877 cw(c117.938,20.829) 117.986,20.877 118.016,20.847 ccw(c118.064,20.895) 118.113,20.847 ccw(c118.064,20.895) 118.113,20.944 cw(c118.191,21.022) 118.113,21.101 118.654,21.642 119.796,22.784 119.796,24.036 R116.2@120.113,24.354 120.113,24.816 120.261,24.963 C474.2@120.261,25.159
HDMI0_TX3_PORT/eDP0_TX_D3_N: C481.1 U3.AH2 | length 66.6
  Top Layer 1 _Signal w0.111: C481.1@104.044,26.029 104.044,26.224 104.41,26.59 104.41,27.376 v1(104.338,27.448) ; v1(136.013,69.004) 136.013,69.082 136.124,69.193 136.124,69.472 139.766,73.114 139.92,73.269 141.09,73.269 141.718,72.641 142.636,72.641 142.723,72.728 U3.AH2@142.779,72.728
  L3_Signals w0.092: v1(104.338,27.448) 104.487,27.597 104.487,29.01 104.487,29.056 ccw(c104.395,29.056) 104.395,29.149 104.205,29.149 cw(c104.205,29.22) 104.205,29.292 104.415,29.292 ccw(c104.415,29.364) 104.415,29.435 104.226,29.435 cw(c104.226,29.507) 104.226,29.578 104.415,29.578 ccw(c104.415,29.65) 104.415,29.722 104.395,29.722 cw(c104.395,29.793) 104.395,29.865 ccw(c104.395,29.957) 104.487,29.957 104.487,31.408 104.487,37.478 v1(136.013,69.004)
HDMI0_TX3_PORT/eDP0_TX_D3_P: C480.1 U3.AH3 | length 66.7
  Top Layer 1 _Signal w0.111: v1(104.822,27.448) 104.75,27.376 104.75,26.583 105.116,26.217 C480.1@105.116,26.021 ; v1(136.497,69.004) 136.497,69.082 136.387,69.193 136.387,69.363 140.029,73.005 140.981,73.005 141.609,72.377 143.03,72.377 143.38,72.728 U3.AH3@143.429,72.728
  L3_Signals w0.092: v1(104.822,27.448) 104.783,27.487 104.783,31.422 104.783,31.612 cw(c104.875,31.612) 104.875,31.704 105.043,31.704 ccw(c105.043,31.776) 105.043,31.847 104.854,31.847 cw(c104.854,31.919) 104.854,31.991 105.034,31.991 ccw(c105.034,32.062) 105.034,32.134 104.875,32.134 cw(c104.875,32.226) 104.783,32.226 104.783,34.578 104.783,37.29 v1(136.497,69.004)
HDMI0_TX3_PORT_N: C481.2 HDMI1.12 R117.2 U21.5 U21.6 | length 17.5
  Top Layer 1 _Signal w0.111: C481.2@104.044,25.499 103.989,25.443 103.989,24.773 R117.2@103.908,24.692 104.06,24.541 104.117,24.541 104.421,24.237 104.421,22.952 104.703,22.67 104.839,22.534 cw(c104.76,22.455) 104.839,22.377 104.729,22.268 ccw(c104.778,22.219) 104.729,22.171 ccw(c104.778,22.219) 104.826,22.171 104.965,22.311 cw(c105.014,22.262) 105.062,22.311 cw(c105.014,22.262) 105.062,22.214 104.974,22.127 ccw(c105.023,22.079) 104.974,22.03 ccw(c105.023,22.079) 105.071,22.03 105.128,22.088 cw(c105.206,22.009) 105.285,22.088 106.049,21.324 107.924,19.448 107.924,17.243 U21.6@107.899,17.218 107.899,15.633 110.2,13.332 110.2,12.836 109.987,12.622 109.987,11.807 HDMI1.12@109.925,11.745
HDMI0_TX3_PORT_P: C480.2 HDMI1.10 R118.2 U21.4 U21.7 | length 17.5
  Top Layer 1 _Signal w0.111: C480.2@105.116,25.491 105.116,25.296 105.094,25.273 R118.2@105.094,24.708 104.76,24.375 104.76,23.092 105.91,21.943 106.212,21.641 ccw(c106.291,21.719) 106.369,21.641 ; 106.37,21.641 cw(c106.418,21.593) 106.466,21.641 cw(c106.418,21.593) 106.466,21.545 106.435,21.514 ccw(c106.484,21.466) 106.435,21.417 ccw(c106.484,21.466) 106.532,21.417 106.577,21.462 cw(c106.625,21.414) 106.673,21.462 cw(c106.625,21.414) 106.673,21.366 106.628,21.321 ccw(c106.676,21.273) 106.628,21.225 ccw(c106.676,21.273) 106.725,21.225 106.769,21.269 cw(c106.818,21.221) 106.866,21.269 cw(c106.818,21.221) 106.866,21.173 106.821,21.128 ccw(c106.869,21.08) 106.821,21.032 ccw(c106.869,21.08) 106.918,21.032 106.962,21.076 cw(c107.011,21.028) 107.059,21.076 cw(c107.011,21.028) 107.059,20.98 107.044,20.965 ccw(c107.123,20.887) 107.044,20.808 107.18,20.673 108.264,19.589 108.264,17.742 108.37,17.635 108.37,17.247 108.444,17.174 108.444,16.887 108.455,16.876 108.455,15.558 110.54,13.473 110.54,12.987 110.884,12.642 110.884,11.787 HDMI1.10@110.926,11.745
HDMI0_TX_CEC_PORT: HDMI1.13 Q12.3 | length 32.9
  Top Layer 1 _Signal w0.254: HDMI1.13@109.425,11.745 v1(109.425,13.296)
  Top Layer 1 _Signal w0.381: Q12.3@113.751,32.247 113.751,32.072 113.886,31.937 114.061,31.937 114.563,31.435 v1(121.515,31.435)
  L3_Signals w0.254: v1(109.425,13.296) 121.515,25.386 v1(121.515,31.435)
HDMI0_TX_ON_H: Q7.1 Q8.1 Q9.1 Q10.1 | length 23.8
  Top Layer 1 _Signal w0.508: Q10.1@103.027,27.012 103.027,28.772 103.324,29.069 107.554,29.069 108.058,28.566 ; Q7.1@108.058,26.9 108.058,28.566 ; Q8.1@113.165,26.863 113.165,28.799 113.543,29.177 117.301,29.177 118.184,28.294 Q9.1@118.184,26.607 ; 113.165,28.467 112.4,29.232 108.421,29.232 108.058,28.868 108.058,28.566
HDMI0_TX_SBD/eDP0_TX_AUX_N: C469.2 U3.AG1 | length 78.3
  Top Layer 1 _Signal w0.161: C469.2@105.035,17.748 105.035,17.968 105.402,18.335 105.402,18.778 v1(105.317,18.863)
  Top Layer 1 _Signal w0.203: v1(141.85,73.082) 141.85,73.09 142.129,73.37 U3.AG1@142.129,73.378
  Bottom Layer_Signals w0.161: v1(105.317,18.863) 105.413,18.959 105.413,20.046 105.026,20.433 102.321,20.433 101.807,20.948 101.807,23.988 103.26,25.441 103.942,25.441 110.576,32.074 110.576,34.818 110.443,34.951 110.443,35.513 110.576,35.646 110.576,45.073 136.075,70.572 136.075,71.023 136.166,71.115 137.39,72.339 141.107,72.339 v1(141.85,73.082)
HDMI0_TX_SBD/eDP0_TX_AUX_P: C465.2 U3.AG2 | length 78.6
  Top Layer 1 _Signal w0.161: v1(105.8,18.863) 105.715,18.778 105.715,18.33 106.082,17.964 C465.2@106.082,17.743
  Top Layer 1 _Signal w0.203: v1(142.405,72.982) 142.405,72.992 142.779,73.367 U3.AG2@142.779,73.378
  Bottom Layer_Signals w0.161: v1(105.8,18.863) 105.726,18.937 105.726,20.176 105.156,20.747 102.451,20.747 102.12,21.078 102.12,23.858 103.39,25.127 104.072,25.127 110.889,31.944 110.889,34.948 110.756,35.081 110.756,35.383 110.889,35.516 110.889,44.943 136.388,70.442 136.388,70.893 137.52,72.025 141.448,72.025 v1(142.405,72.982)
HDMI0_TX_SCL_PORT: HDMI1.15 Q6.3 R106.1 | length 26.6
  Top Layer 1 _Signal w0.254: HDMI1.15@108.425,11.745 v1(108.425,13.374)
  Top Layer 1 _Signal w0.508: v1(108.125,31.923) 108.125,32.172 108.545,32.592 Q6.3@108.545,32.767 110.337,32.767 R106.1@111.121,33.55
  L3_Signals w0.254: v1(108.125,31.923) 106.379,30.177 106.379,13.866 106.871,13.374 v1(108.425,13.374)
HDMI0_TX_SDA_PORT: HDMI1.16 Q11.3 R108.1 | length 37.9
  Top Layer 1 _Signal w0.254: HDMI1.16@107.925,11.745 v1(107.925,14.265)
  Top Layer 1 _Signal w0.381: R108.1@114.607,38.486 116.672,38.486 117.026,38.84 Q11.3@117.026,39.015 117.911,39.015 v1(120.536,36.39)
  L3_Signals w0.254: v1(107.925,14.265) 108.753,14.265 120.74,26.253 120.74,36.185 v1(120.536,36.39)
HDMI_RX_CLKN: U3.AF5
HDMI_RX_CLKP: U3.AF6
HDMI_RX_D0N: U3.AG4
HDMI_RX_D0P: U3.AG5
HDMI_RX_D1N: U3.AH5
HDMI_RX_D1P: U3.AH6
HDMI_RX_D2N: U3.AJ4
HDMI_RX_D2P: U3.AJ5
HDMI_TX0_REXT: R99.2 U3.AM2 | length 1.5
  Top Layer 1 _Signal w0.203: v1@142.477,69.757 v1(142.454,69.78) 142.508,69.78 142.75,70.023 142.802,70.023 142.802,70.106 U3.AM2@142.779,70.128
  Bottom Layer_Signals w0.203: v1(142.454,69.78) 143.047,69.78 143.106,69.721 143.156,69.721 143.229,69.648 R99.2@143.229,69.598
HDMITX0_CEC_M0: Q12.2 R119.1 U3.AK24 | length 66.9
  Top Layer 1 _Signal w0.254: v1(156.819,71.175) 156.823,71.175 157.076,71.428 U3.AK24@157.079,71.428
  Top Layer 1 _Signal w0.381: v1(111.682,37.37) 111.678,37.366 111.609,37.366 110.663,36.42 R119.1@110.642,36.42 110.737,36.325 110.898,36.325 112.801,34.422 Q12.2@112.801,34.247
  Bottom Layer_Signals w0.254: v1(111.682,37.37) 111.682,41.868 135.714,65.901 145.514,65.901 147.192,67.579 147.192,67.622 148.87,69.3 149.194,69.3 149.434,69.541 149.775,69.541 149.917,69.399 153.968,69.399 155.744,71.175 v1(156.819,71.175)
HDMITX0_HPDIN_M0: Q4.3 R100.1 U3.B26 | length 78.8
  Top Layer 1 _Signal w0.132: Q4.3@125.695,30.901 125.832,31.038 125.832,31.214 v1(125.832,32.628)
  Top Layer 1 _Signal w0.203: v1(158.047,89.287) 158.047,89.296 U3.B26@158.379,89.628
  Top Layer 1 _Signal w0.508: R100.1@123.323,30.84 123.323,30.842 123.695,31.214 Q4.3@125.624,31.214
  L6_Signals w0.106: v1(125.832,32.628) 125.832,40.034 136.775,50.978 136.775,51.007 147.96,62.192 147.96,63.731 147.917,63.774 147.917,64.053 147.96,64.095 147.96,67.255 149.498,68.793 149.744,68.793 149.941,68.991 149.941,69.237 150.636,69.931 150.636,70.651 151.217,71.233 151.217,71.265 151.988,72.036 152.444,72.036 152.997,72.588 153.03,72.588 154.48,74.039 154.48,74.823 155.813,76.155 155.813,76.479 155.77,76.522 155.77,76.716 155.707,76.778 155.707,77.058 155.77,77.12 155.77,81.541 156.702,82.473 157.505,82.473 157.722,82.256 157.722,82.032 157.939,81.815 158.825,81.815 159.023,82.012 159.023,82.291 158.879,82.435 158.879,82.523 159.019,82.663 159.019,84.645 159.035,84.661 159.035,84.94 159.019,84.956 159.019,85.45 158.047,86.421 158.047,87.593 157.718,87.922 157.718,88.101 157.677,88.142 157.677,88.917 v1(158.047,89.287)
HDMITX0_SCL_M0: Q6.2 R107.2 U3.AJ28 | length 83.3
  Top Layer 1 _Signal w0.132: v1(159.348,71.754) 159.352,71.754 159.676,72.078 U3.AJ28@159.679,72.078
  Top Layer 1 _Signal w0.381: Q6.2@107.595,34.767 107.595,36.253 107.789,36.447 R107.2@107.814,36.447 107.814,38.036 114.231,44.453 151.32,44.453 159.612,52.745 159.612,58.373 159.63,58.391 v1@159.625,58.396
  L3_Signals w0.132: v1(159.348,71.754) 157.994,71.754 157.377,71.137 157.377,67.652 159.218,65.811 159.218,59.255 159.623,58.849 159.623,58.411 v1(159.634,58.4)
HDMITX0_SDA_M0: C482.1 Q11.2 R114.2 U3.AJ25 | length 65.4
  Top Layer 1 _Signal w0.132: v1(157.443,71.792) U3.AJ25@157.729,72.078
  Top Layer 1 _Signal w0.381: Q11.2@116.076,41.015 116.118,41.057 116.118,41.829 116.125,41.836 116.125,41.948 116.836,42.658 116.836,43.009 117.279,43.452 120.023,43.452 120.813,42.662 R114.2@120.813,40.731
  Bottom Layer_Signals w0.254: v1(116.122,41.832) 116.122,44.884 136.492,65.255 146.05,65.255 147.666,66.871 147.899,66.871 147.939,66.831 148.997,66.831 149.037,66.871 153.096,66.871 156.256,70.03 156.494,70.03 156.517,70.008 156.857,70.008 157.436,70.587 157.436,71.785 v1(157.443,71.792)
I2C0_SCL_M2: U3.W30 U22.A3 U23.A3 | length 151.3
  Top Layer 1 _Signal w0.254: v1(160.654,78.23) 160.658,78.234 160.658,78.239 160.979,78.56 U3.W30@160.979,78.578 U3.W30@160.979,78.575 ; 168.963,71.864 167.923,70.823 167.923,63.147 164.552,59.776 164.552,58.298 168.188,54.662 168.188,29.935 175.487,22.637 175.487,11.617 176.267,10.836 180.064,10.836 180.264,10.637 180.264,9.38 180.253,9.369 U23.A3@180.253,8.514 ; 192.134,30.722 192.198,30.658 U22.A3@192.198,30.261
  Top Layer 1 _Signal w0.381: v1(169.49,72.355) 169.49,72.35 168.983,71.843 168.983,42.914 180.768,31.129 190.332,31.129 190.399,31.062 191.898,31.062 192.121,30.839 192.121,30.735 192.134,30.722
  L5_POWER w0.254: v1(160.654,78.23) 160.654,78.27 160.727,78.343 160.727,78.373 161.077,78.722 161.077,79.29 160.953,79.413 160.953,79.823 162.098,80.968 162.678,80.968 163.425,81.715 164.956,81.715 165.161,81.51 165.501,81.51 165.595,81.605 165.806,81.605 168.682,78.728 168.682,74.876 169.639,73.919 169.639,73.231 169.49,73.082 v1(169.49,72.355)
I2C0_SDA_M2: U3.W29 U22.B1 U23.B1 | length 92.4
  Top Layer 1 _Signal w0.132: v1(160.06,78.291) 160.06,78.3 160.329,78.569 U3.W29@160.329,78.578 ; v1(190.91,29.768) 190.982,29.768 191.075,29.861 U22.B1@191.399,29.861
  Top Layer 1 _Signal w0.254: v1(178.184,9.304) 178.187,9.302 178.187,8.638 178.711,8.114 U23.B1@179.453,8.114
  L6_Signals w0.106: v1(160.06,78.291) 160.06,77.285 160.072,77.273 160.072,76.678 160.06,76.667 160.06,76.05 161.02,75.09 161.02,73.719 165.818,68.921 165.818,55.094 165.818,53.656 188.199,31.275 189.992,31.275 190.926,30.342 190.926,29.784 v1(190.91,29.768)
  Bottom Layer_Signals w0.254: v1(178.184,9.304) 178.632,8.857 179.226,8.857 185.068,14.699 185.068,19.89 190.91,25.732 v1(190.91,29.768)
I2C1_SCL_M2: U3.V29 U24.A3 | length 54.2
  Top Layer 1 _Signal w0.132: U3.V29@160.329,79.228 v1(160.666,78.892) ; U24.A3@185.247,38.557 185.807,38.557 185.896,38.646 v1(185.969,38.646)
  L6_Signals w0.106: v1(160.666,78.892) 161.118,78.44 161.118,78.437 162.922,76.633 162.922,75.215 162.876,75.169 162.876,74.927 162.98,74.822 162.98,74.602 162.891,74.512 162.891,74.233 162.98,74.144 162.98,72.103 166.054,69.029 166.054,55.127 177.453,43.728 180.514,40.668 180.766,40.668 180.963,40.47 180.963,40.218 182.48,38.702 185.913,38.702 v1(185.969,38.646)
I2C1_SDA_M2: U3.V28 U24.B1 | length 62.6
  Top Layer 1 _Signal w0.152: v1(159.232,79.623) 159.268,79.587 159.321,79.587 U3.V28@159.679,79.228
  Top Layer 1 _Signal w0.254: v1(169.801,71.839) 169.801,71.8 169.629,71.627 169.629,58.438 170.54,57.527 170.576,57.527 184.847,43.255 184.847,40.353 ; U24.B1@184.847,39.357 184.847,40.011 ; 184.848,40.011 184.848,40.352
  L5_POWER w0.152: v1(159.232,79.623) 159.232,79.69 159.352,79.81 159.352,79.895 159.967,80.511 160.156,80.511 160.772,81.127 160.772,81.457 161.316,82.001 161.316,82.297 162.286,83.267 165.824,83.267 167.458,81.633 167.458,81.551 171.547,77.461 171.547,73.585 v1(169.801,71.839)
I2C6_SCL_M0: R301.1 U3.W31 U6.6 | length 31.9
  Top Layer 1 _Signal w0.254: U3.W31@161.629,78.578 161.953,78.254 v1(161.961,78.254)
  Top Layer 1 _Signal w0.508: R301.1@185.807,69.214 v1(186.335,68.686) U6.6@186.335,66.832
  L3_Signals w0.152: v1(161.961,78.254) 161.926,78.218 161.926,77.538 162.334,77.13 164.705,77.13 165.013,76.823 165.572,76.823 167.121,75.274 167.121,75.234 170.492,71.863 183.019,71.863 186.148,68.733 186.288,68.733 v1(186.335,68.686)
I2C6_SDA_M0: R304.1 U3.V31 U6.5 | length 39
  Top Layer 1 _Signal w0.254: U3.V31@161.629,79.228 161.629,79.223 161.917,78.935 v1(161.917,78.93)
  Top Layer 1 _Signal w0.508: R304.1@185.769,70.336 186.785,70.336 187.605,69.516 U6.5@187.605,66.832
  L3_Signals w0.152: v1(161.917,78.93) 161.898,78.949 161.136,78.949 161.004,79.082 161.004,79.733 161.215,79.944 161.545,79.944 162.541,80.94 162.855,80.94 163.128,81.213 163.518,81.213 164.35,80.381 166.476,80.381 170.872,75.984 170.872,75.212 170.606,74.946 170.606,74.82 171.579,73.847 171.579,73.243 171.668,73.154 183.866,73.154 v1(186.629,70.391)
ICMCT: R397.2 U45.14 | length 3.9
  Top Layer 1 _Signal w0.152: U45.14@281.874,34.703 282.815,34.703 283.194,34.324 R397.2@285.614,34.324
LCD_PWREN_H: R135.1 U3.U33 U27.4 | length 85.3
  Top Layer 1 _Signal w0.132: U3.U33@162.929,79.878 162.965,79.914 163.177,79.914 163.451,80.188 163.677,80.188 163.853,80.364 164.122,80.364 v1(164.499,80.741)
  Top Layer 1 _Signal w0.457: v1(172.1,76.635) 173.443,75.293 173.443,61.733 187.801,47.374 187.801,39.84 193.719,33.922 199.505,33.922 202.756,30.671 202.756,26.152 199.291,22.687 199.046,22.687 198.999,22.64 R135.1@198.999,22.615 199.003,22.611 199.003,21.378 U27.4@199.007,21.375
  L3_Signals w0.254: v1(164.499,80.741) 169.718,80.741 172.066,78.393 172.066,76.67 v1(172.1,76.635)
LEDMODE: R395.1 U45.42 | length 2.6
  Top Layer 1 _Signal w0.254: R395.1@272.581,36.734 272.581,36.75 272.691,36.861 273.173,36.861 273.326,37.014 274.579,37.014 274.768,37.203 U45.42@274.974,37.203
LM_FB: C193.2 R296.1 R300.2 R302.2 U62.8 | length 15.4
  Top Layer 1 _Signal w0.254: C193.2@36.878,69.468 35.53,69.468 R302.2@35.411,69.587 35.261,69.587 34.104,68.43 34.104,66.895 34.372,66.627 36.773,66.627 38.627,64.773 38.63,64.773 39.064,64.34 39.764,64.34 U62.8@39.768,64.336 41.53,64.336 42.985,65.791 R300.2@42.987,65.791
MDC: U1.B3 U45.37 | length 50
  Top Layer 1 _Signal w0.132: U1.B3@278.581,80.08 278.956,80.455 279.506,80.455 279.878,80.828 280.145,80.828 v1(280.161,80.844)
  Top Layer 1 _Signal w0.254: v1(273.903,40.463) 273.903,39.931 274.13,39.703 U45.37@274.974,39.703
  L8_Signals w0.132: v1(273.903,40.463) 273.903,42.717 274.58,43.394 274.58,43.636 274.785,43.841 275.027,43.841 276.517,45.33 276.517,45.993 276.401,46.108 276.401,54.786 283.236,61.62 283.236,75.937 283.42,76.121 283.42,76.411 283.236,76.595 283.236,78.348 281.323,80.261 281.085,80.261 280.88,80.466 280.88,80.705 280.741,80.844 v1(280.161,80.844)
MDC_1: U1.M3
MDINTn: U1.C2
MDINTn_1: U1.N3
MDIO: U1.C1 U45.38 | length 51.2
  Top Layer 1 _Signal w0.132: v1(272.977,40.259) 272.977,40.207 273.981,39.203 U45.38@274.974,39.203 ; U1.C1@277.801,81.68 U1.C1@277.781,81.68 277.781,81.644 278.133,81.292 v1(278.133,81.257)
  L8_Signals w0.132: v1(272.977,40.259) 272.977,40.721 273.554,41.298 273.554,42.475 273.602,42.523 273.602,42.72 274.365,43.483 274.365,43.725 274.696,44.056 274.937,44.056 276.186,45.305 276.186,45.498 276.301,45.614 276.301,45.903 276.186,46.018 276.186,55.124 282.798,61.737 282.798,76.044 282.72,76.121 282.72,76.411 282.798,76.488 282.798,78.121 281.141,79.778 279.612,79.778 v1(278.133,81.257)
MDIO_VSC: IC.4 U50.N2 | length 228.9
  Top Layer 1 _Signal w0.254: v1(57.55,119.112) 57.55,119.951 58.065,120.465 58.313,120.465 IC.4@58.34,120.492
  Top Layer 1 _Signal w0.381: v1(256.146,60.99) 256.411,60.724 256.411,58.902 256.919,58.394 U50.N2@256.919,58.379
  L8_Signals w0.381: v1(57.55,119.112) 63.874,112.789 84.04,112.789 85.605,114.354 186.514,114.354 232.547,68.322 237.138,68.322 237.281,68.179 237.674,68.179 237.817,68.322 246.548,68.322 253.338,61.532 255.598,61.532 256.14,60.99 v1(256.146,60.99)
MODE0: R385.1 R386.2 U1.J19 U45.33 | length 33
  Top Layer 1 _Signal w0.132: v1(272.383,64.484) 272.383,64.557 272.476,64.651 272.476,64.689 272.981,65.194 U1.J19@272.981,67.28 ; v1(272.875,45.862) 272.875,44.814 273.375,44.313 273.375,44.303 273.546,44.133 R386.2@273.556,44.133 274.248,44.133 ; 274.249,44.132 274.558,44.132 R385.1@274.565,44.14 274.683,44.022 274.909,44.022 277.174,41.757 U45.33@277.174,40.403
  L3_Signals w0.113: v1(272.383,64.484) 272.6,64.267 272.6,64.174 272.538,64.113 272.538,55.975 272.538,55.919 272.771,55.919 272.771,55.781 272.513,55.781 272.513,55.643 272.771,55.643 272.771,55.505 272.513,55.505 272.513,55.367 272.771,55.367 272.771,55.23 272.513,55.23 272.513,55.092 272.771,55.092 272.771,54.954 272.513,54.954 272.513,54.816 272.771,54.816 272.771,54.678 272.513,54.678 272.513,54.54 272.771,54.54 272.771,54.402 272.513,54.402 272.513,54.264 272.538,54.264 272.538,54.105 272.538,46.361 272.82,46.079 272.82,45.917 v1(272.875,45.862)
